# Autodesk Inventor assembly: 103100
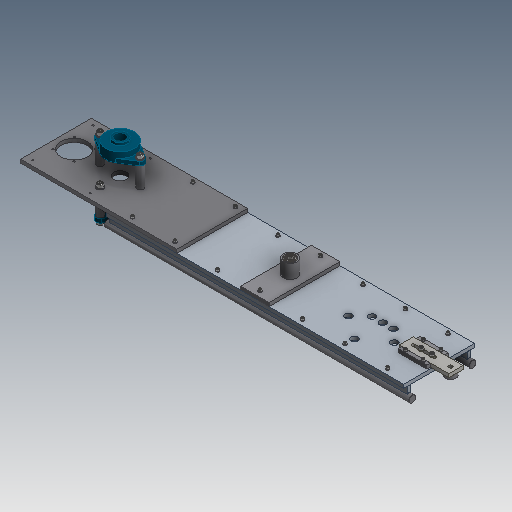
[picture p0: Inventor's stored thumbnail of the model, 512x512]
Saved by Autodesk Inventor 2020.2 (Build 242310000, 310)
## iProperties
Created: 2000-10
Part Number: 103100
Document SubType Name: Assembly
Designer: wymerj
Mass: 43095.1 g
Surface Area: 15307.4 cm^2
Volume: 8124.2 cm^3
Density: 5.30453 g/cm^3
Control State: 0
Master: False
Checked Out: False
Shininess: 0.0
Length Units: 11269
Angle Units: 11279
Time Units: 11290
Mass Units: 11283
Length Display Precision: 3
Angle Display Precision: 2
Compacted: True
Dimensions: 254x252,4x1434 mm
Mass: 43,095 kg
Density: 0.0
Volumn: 0.0
Area: 0.0
PropertySet Name: Model Information
Author: wymerj
Revision Number: -
Title: 103100
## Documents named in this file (17)
- D:\07 - DEMODATEN\OTX 2019 - Dataset - UPDATE - Dez2019\Designs\07-Packing machine\103100.iam
- D:\07 - DEMODATEN\OTX 2019 - Dataset - UPDATE - Dez2019\Designs\07-Packing machine\Parts\ADSK-011406.ipt
- D:\07 - DEMODATEN\OTX 2019 - Dataset - UPDATE - Dez2019\Designs\07-Packing machine\Parts\ADSK-011348.ipt
- D:\07 - DEMODATEN\OTX 2019 - Dataset - UPDATE - Dez2019\Designs\07-Packing machine\Parts\ADSK-011713.ipt
- D:\07 - DEMODATEN\OTX 2019 - Dataset - UPDATE - Dez2019\Designs\07-Packing machine\Parts\ADSK-011346.ipt
- D:\07 - DEMODATEN\OTX 2019 - Dataset - UPDATE - Dez2019\Designs\07-Packing machine\500594.iam
- D:\07 - DEMODATEN\OTX 2019 - Dataset - UPDATE - Dez2019\Designs\07-Packing machine\Parts\ADSK-011347.ipt
- D:\07 - DEMODATEN\OTX 2019 - Dataset - UPDATE - Dez2019\Designs\07-Packing machine\Parts\ADSK-011344.ipt
- D:\07 - DEMODATEN\OTX 2019 - Dataset - UPDATE - Dez2019\Designs\07-Packing machine\500367.iam
- D:\07 - DEMODATEN\OTX 2019 - Dataset - UPDATE - Dez2019\Designs\07-Packing machine\Parts\ADSK-011676.ipt
- D:\07 - DEMODATEN\OTX 2019 - Dataset - UPDATE - Dez2019\Content Center Files\de-DE\DIN 125-1  B\DIN 125-1 - B 13.ipt
- D:\07 - DEMODATEN\OTX 2019 - Dataset - UPDATE - Dez2019\Content Center Files\de-DE\ISO 4762(2)\ISO 4762 - M12 x 45ISO.ipt
- D:\07 - DEMODATEN\OTX 2019 - Dataset - UPDATE - Dez2019\Content Center Files\de-DE\DIN 125-1  B\DIN 125-1 - B 6,4.ipt
- D:\07 - DEMODATEN\OTX 2019 - Dataset - UPDATE - Dez2019\Content Center Files\de-DE\ISO 4762(2)\ISO 4762 - M6 x 60ISO.ipt
- D:\07 - DEMODATEN\OTX 2019 - Dataset - UPDATE - Dez2019\Content Center Files\de-DE\ISO 4762(2)\ISO 4762 - M6 x 25ISO.ipt
- D:\07 - DEMODATEN\OTX 2019 - Dataset - UPDATE - Dez2019\Content Center Files\de-DE\DIN 125-1  B\DIN 125-1 - B 8,4.ipt
- D:\07 - DEMODATEN\OTX 2019 - Dataset - UPDATE - Dez2019\Content Center Files\de-DE\ISO 4762(2)\ISO 4762 - M8 x 25ISO.ipt
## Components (73 placed, 16 different names)
1. ADSK-011348:1 — Insert:1, Insert:2, Insert:3, Insert:4, Passend:13, Passend:18, Passend:19, Passend:20
2. ADSK-011406:1 — Insert:2, Mate:1
3. ADSK-011406:2 — Insert:1, Insert:5
4. ADSK-011406:3 — Insert:3, Insert:6
5. ADSK-011406:4 — Insert:4, Mate:2
6. ADSK-011713:1 — Insert:5, Mate:1
7. ADSK-011713:2 — Insert:6, Mate:2, Passend:15, Passend:17
8. ADSK-011346:1 — Insert:8, Mate:4, Insert:9, Mate:5, Insert:10, Mate:6, Insert:11, Mate:9, Insert:12, Mate:10, Insert:13, Mate:11, Passend:18, Passend:19, Passend:20, Passend:21, Passend:22, Passend:23, Einfügen:49, Einfügen:50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
9. 500594:1 [sub-assembly] — Insert:8, Mate:4
10. ADSK-011347:1 — Insert:9, Mate:5, Tangent:3, Tangent:4, Mate:8
11. ADSK-011347:2 — Insert:10, Mate:6, Tangent:1, Tangent:2, Mate:7
12. ADSK-011344:1 — Tangent:1, Tangent:2, Mate:7
13. ADSK-011344:2 — Tangent:3, Tangent:4, Mate:8
14. 500367:1 [sub-assembly] — Insert:11, Mate:9, Passend:21, Passend:22, Passend:23, Passend:25, Passend:27, Fluchtend:1
15. ADSK-011676:1 — Insert:12, Mate:10
16. ADSK-011676:2 — Insert:13, Mate:11
17. DIN 125-1 B B 13:1 — Passend:13
18. DIN 125-1 B B 13:2
19. DIN 125-1 B B 13:3
20. DIN 125-1 B B 13:4
21. DIN 125-1 B B 13:5
22. DIN 125-1 B B 13:6
23. DIN 125-1 B B 13:7
24. ISO 4762 M12 x 45:1
25. ISO 4762 M12 x 45:2
26. ISO 4762 M12 x 45:3 — Passend:15
27. ISO 4762 M12 x 45:4 — Passend:17
28. ISO 4762 M12 x 45:5
29. ISO 4762 M12 x 45:6
30. ISO 4762 M12 x 45:7
31. ISO 4762 M12 x 45:8
32. DIN 125-1 B B 6,4:1
33. DIN 125-1 B B 6,4:2
34. DIN 125-1 B B 6,4:3
35. DIN 125-1 B B 6,4:4
36. ISO 4762 M6 x 60:1
37. ISO 4762 M6 x 60:2
38. ISO 4762 M6 x 60:3
39. ISO 4762 M6 x 60:4
40. DIN 125-1 B B 6,4:5 — Einfügen:37
41. DIN 125-1 B B 6,4:6 — Einfügen:36
42. ISO 4762 M6 x 60:5 — Einfügen:36
43. ISO 4762 M6 x 60:6 — Einfügen:37
44. DIN 125-1 B B 6,4:20
45. DIN 125-1 B B 6,4:21
46. DIN 125-1 B B 6,4:22
47. ISO 4762 M6 x 60:7
48. DIN 125-1 B B 6,4:23 — Einfügen:49
49. ISO 4762 M6 x 60:8
50. DIN 125-1 B B 6,4:24 — Einfügen:50
51. ISO 4762 M6 x 60:9
52. DIN 125-1 B B 6,4:25 — Einfügen:51
53. ISO 4762 M6 x 60:10
54. DIN 125-1 B B 6,4:26 — Einfügen:52
55. ISO 4762 M6 x 60:11
56. DIN 125-1 B B 6,4:27 — Einfügen:53
57. ISO 4762 M6 x 60:12
58. DIN 125-1 B B 6,4:28 — Einfügen:56
59. ISO 4762 M6 x 60:13
60. DIN 125-1 B B 6,4:29 — Einfügen:57
61. ISO 4762 M6 x 60:14
62. DIN 125-1 B B 6,4:30
63. DIN 125-1 B B 6,4:31
64. DIN 125-1 B B 6,4:32
65. DIN 125-1 B B 6,4:33
66. ISO 4762 M6 x 25:1
67. ISO 4762 M6 x 25:2
68. ISO 4762 M6 x 25:3
69. ISO 4762 M6 x 25:4
70. DIN 125-1 B B 8,4:1 — Passend:25
71. DIN 125-1 B B 8,4:2 — Passend:27
72. ISO 4762 M8 x 25:1
73. ISO 4762 M8 x 25:2
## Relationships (47: Insert 21, Mate 21, Tangent 4, Flush 1)
- Insert:1: ADSK-011348:1 ↔ ADSK-011406:2
- Insert:2: ADSK-011348:1 ↔ ADSK-011406:1
- Insert:3: ADSK-011348:1 ↔ ADSK-011406:3
- Insert:4: ADSK-011348:1 ↔ ADSK-011406:4
- Insert:5: ADSK-011406:2 ↔ ADSK-011713:1
- Mate:1: ADSK-011406:1 ↔ ADSK-011713:1
- Insert:6: ADSK-011406:3 ↔ ADSK-011713:2
- Mate:2: ADSK-011406:4 ↔ ADSK-011713:2
- Insert:8: ADSK-011346:1 ↔ 500594:1
- Mate:4: ADSK-011346:1 ↔ 500594:1
- Insert:9: ADSK-011346:1 ↔ ADSK-011347:1
- Mate:5: ADSK-011346:1 ↔ ADSK-011347:1
- Insert:10: ADSK-011346:1 ↔ ADSK-011347:2
- Mate:6: ADSK-011346:1 ↔ ADSK-011347:2
- Tangent:1: ADSK-011347:2 ↔ ADSK-011344:1
- Tangent:2: ADSK-011347:2 ↔ ADSK-011344:1
- Mate:7: ADSK-011347:2 ↔ ADSK-011344:1
- Tangent:3: ADSK-011347:1 ↔ ADSK-011344:2
- Tangent:4: ADSK-011347:1 ↔ ADSK-011344:2
- Mate:8: ADSK-011347:1 ↔ ADSK-011344:2
- Insert:11: ADSK-011346:1 ↔ 500367:1
- Mate:9: ADSK-011346:1 ↔ 500367:1
- Insert:12: ADSK-011346:1 ↔ ADSK-011676:1
- Mate:10: ADSK-011346:1 ↔ ADSK-011676:1
- Insert:13: ADSK-011346:1 ↔ ADSK-011676:2
- Mate:11: ADSK-011346:1 ↔ ADSK-011676:2
- Passend:13 [Mate]: ADSK-011348:1 ↔ DIN 125-1 B B 13:1
- Passend:15 [Mate]: ADSK-011713:2 ↔ ISO 4762 M12 x 45:3
- Passend:17 [Mate]: ADSK-011713:2 ↔ ISO 4762 M12 x 45:4
- Passend:18 [Mate]: ADSK-011348:1 ↔ ADSK-011346:1
- Passend:19 [Mate]: ADSK-011348:1 ↔ ADSK-011346:1
- Passend:20 [Mate]: ADSK-011348:1 ↔ ADSK-011346:1
- Passend:21 [Mate]: ADSK-011346:1 ↔ 500367:1
- Passend:22 [Mate]: ADSK-011346:1 ↔ 500367:1
- Passend:23 [Mate]: ADSK-011346:1 ↔ 500367:1
- Einfügen:36 [Insert]: DIN 125-1 B B 6,4:6 ↔ ISO 4762 M6 x 60:5
- Einfügen:37 [Insert]: DIN 125-1 B B 6,4:5 ↔ ISO 4762 M6 x 60:6
- Einfügen:49 [Insert]: ADSK-011346:1 ↔ DIN 125-1 B B 6,4:23
- Einfügen:50 [Insert]: ADSK-011346:1 ↔ DIN 125-1 B B 6,4:24
- Einfügen:51 [Insert]: ADSK-011346:1 ↔ DIN 125-1 B B 6,4:25
- Einfügen:52 [Insert]: ADSK-011346:1 ↔ DIN 125-1 B B 6,4:26
- Einfügen:53 [Insert]: ADSK-011346:1 ↔ DIN 125-1 B B 6,4:27
- Einfügen:56 [Insert]: ADSK-011346:1 ↔ DIN 125-1 B B 6,4:28
- Einfügen:57 [Insert]: ADSK-011346:1 ↔ DIN 125-1 B B 6,4:29
- Passend:25 [Mate]: 500367:1 ↔ DIN 125-1 B B 8,4:1
- Passend:27 [Mate]: 500367:1 ↔ DIN 125-1 B B 8,4:2
- Fluchtend:1 [Flush]: ADSK-011346:1 ↔ 500367:1
## Named parameters: d102_d101 = 0, d103_d101 = 0, d104_d101 = 0, d105_d101 = 0, d106_d101 = 0, d112_d101 = 0, d113_d101 = 0
